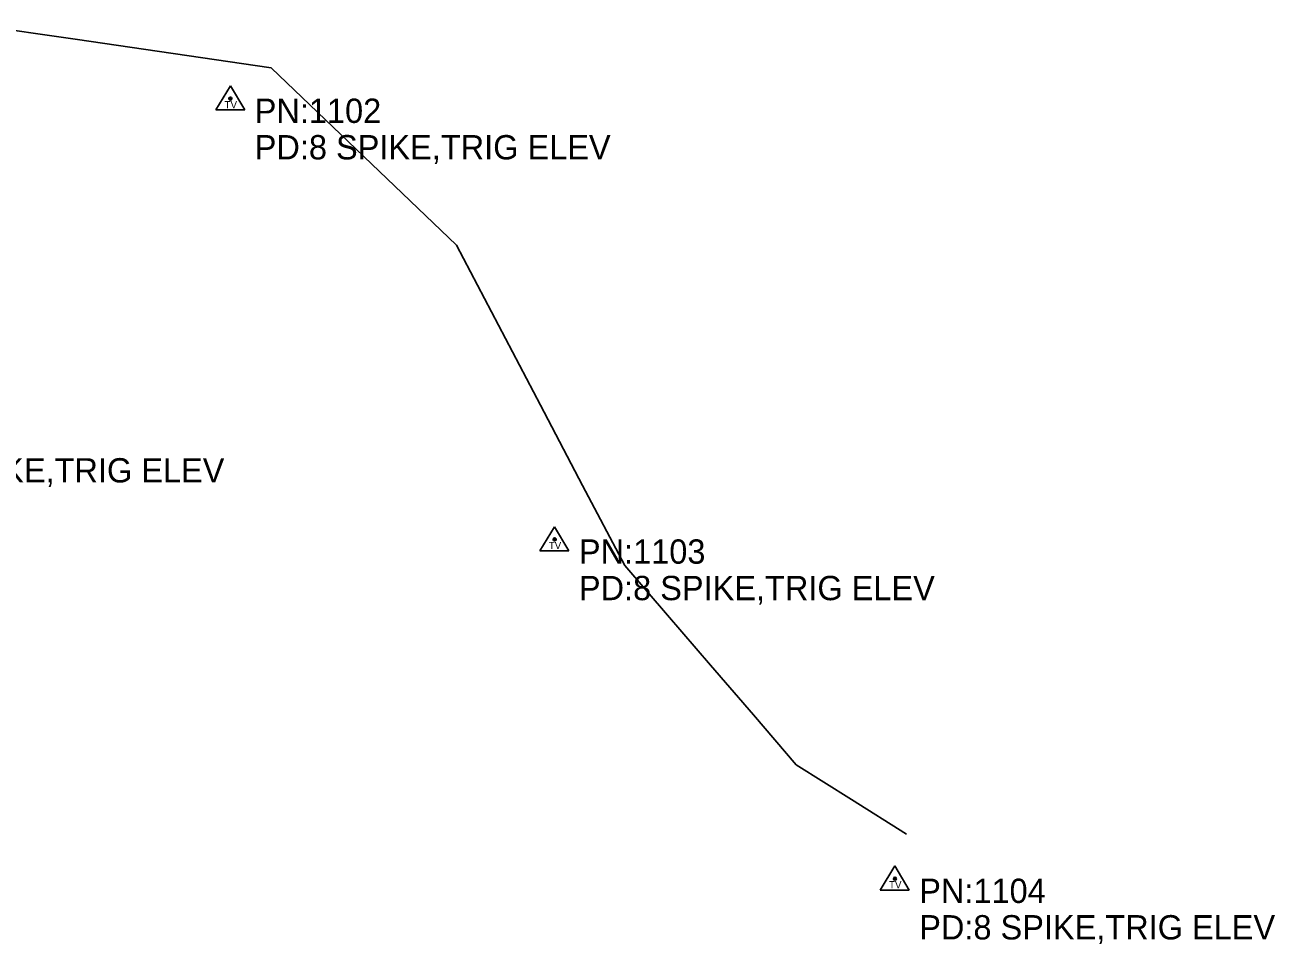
# Model space of a CAD drawing. Extents: x 1445297 to 1476720, y 2042269 to 2057889.
# Drawn here: x 1446189 to 1446446.1, y 2043446.2 to 2043635.2 of the extents above; entities that cross this region are included whole.
import ezdxf

# ---------------------------------------------------------------- set-up
doc = ezdxf.new("R2010")
doc.units = 0
for name, color, linetype in [('S_SECONDARY_CTL', 7, 'Continuous'), ('S_SECONDARY_CTL_ANNOT', 7, 'Continuous'), ('S_TREE', 7, 'Continuous')]:
    doc.layers.add(name, color=color, linetype=linetype)

msp = doc.modelspace()

# ---------------------------------------------------------------- linework, layer by layer
at = {"layer": 'S_SECONDARY_CTL'}
for p, q in [((1446231.23, 2043622.68), (1446228.22, 2043617.73)), ((1446231.23, 2043622.68), (1446234.18, 2043617.73)), ((1446228.22, 2043617.73), (1446234.18, 2043617.73)), ((1446297.91, 2043532.05), (1446294.9, 2043527.1)), ((1446297.91, 2043532.05), (1446300.86, 2043527.1)), ((1446294.9, 2043527.1), (1446300.86, 2043527.1)), ((1446367.9, 2043462.29), (1446364.89, 2043457.33)), ((1446367.9, 2043462.29), (1446370.85, 2043457.33)), ((1446364.89, 2043457.33), (1446370.85, 2043457.33))]:
    msp.add_line(p, q, dxfattribs=at)
for centre, radius in [((1446231.23, 2043620.07), 0.311), ((1446231.23, 2043620.07), 0.183), ((1446231.23, 2043620.07), 0.103), ((1446297.91, 2043529.44), 0.311), ((1446297.91, 2043529.44), 0.183), ((1446297.91, 2043529.44), 0.103), ((1446367.9, 2043459.68), 0.311), ((1446367.9, 2043459.68), 0.183), ((1446367.9, 2043459.68), 0.103)]:
    msp.add_circle(centre, radius, dxfattribs=at)
at = {"layer": 'S_TREE'}
msp.add_lwpolyline([(1446179.17, 2043635.2), (1446199.32, 2043632.27), (1446219.46, 2043629.33), (1446239.61, 2043626.4), (1446249.13, 2043617.29), (1446258.66, 2043608.18), (1446268.19, 2043599.07), (1446277.72, 2043589.97), (1446286.37, 2043573.49), (1446295.03, 2043557.02), (1446303.68, 2043540.55), (1446312.34, 2043524.08), (1446321.15, 2043513.84), (1446329.97, 2043503.6), (1446338.79, 2043493.36), (1446347.6, 2043483.12), (1446358.96, 2043475.97), (1446370.31, 2043468.82)], dxfattribs=at)

# ---------------------------------------------------------------- texts
at = {"layer": 'S_SECONDARY_CTL'}
for p in [(1446230.03, 2043618.06), (1446296.71, 2043527.43), (1446366.69, 2043457.67)]:
    msp.add_text('TV', height=1.5, dxfattribs=at).set_placement(p)
at = {"layer": 'S_SECONDARY_CTL_ANNOT'}
for s, p in [('PN:1102', (1446236.23, 2043615.07)), ('PD:8 SPIKE,TRIG ELEV', (1446236.23, 2043607.57)), ('PD:8 SPIKE,TRIG ELEV', (1446156.8, 2043541.14)), ('PN:1103', (1446302.91, 2043524.44)), ('PD:8 SPIKE,TRIG ELEV', (1446302.91, 2043516.94)), ('PN:1104', (1446372.9, 2043454.68)), ('PD:8 SPIKE,TRIG ELEV', (1446372.9, 2043447.18))]:
    msp.add_text(s, height=5, dxfattribs=at).set_placement(p)

doc.saveas('drawing.dxf')
